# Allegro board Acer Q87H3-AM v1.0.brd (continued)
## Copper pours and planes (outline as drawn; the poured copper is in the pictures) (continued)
GND on TOP (solid shape): 141.51,243.11 141.51,234.09 140.62,233.2 129.06,233.2 127.79,231.93 127.79,222.43 126.89,221.53 126.89,219.4 126.65,219.16 126.65,217.56 126.55,217.46 125.94,217.46 125.84,217.56 125.84,220.48 124.87,221.44 124.87,222.16 124.11,222.92 124.11,223.81 125.76,225.46 125.76,227.49 124.62,228.63 124.62,236.25 125.51,237.14 125.51,243.11 125.89,243.49 141.13,243.49
GND on TOP (solid shape): 119.03,20.61 119.03,16.92 119.29,16.67 121.06,16.67 121.44,17.05 121.44,17.56 121.57,17.69 122.33,17.69 122.59,17.94 122.59,18.45 122.71,18.57 126.27,18.57 128.56,16.29 128.56,15.5 128.43,15.37 127.67,15.37 127.16,15.88 125.46,15.88 125.23,15.65 114,15.65 113.77,15.88 112.83,15.88 112.61,15.65 108.16,15.65 107.91,15.91 107.91,16.8 108.16,17.05 113.06,17.05 113.82,17.81 116.11,17.81 116.36,18.07 116.36,20.73 116.49,20.86 118.78,20.86
GND on TOP (solid shape): 30.77,71.15 31.78,71.15 32.42,70.52 31.78,69.88 30.77,69.88 30.77,66.71 27.72,66.71 27.72,69.88 26.7,69.88 26.07,70.52 26.7,71.15 27.72,71.15 27.72,75.6 30.77,75.6
GND on TOP (solid shape): 55.1,89.75 55.1,89.38 55.08,89.36 55.01,89.27 54.99,89.15 55.12,88.91 55.4,88.9 55.42,88.91 55.59,88.85 55.74,88.7 55.79,88.7 55.83,88.66 55.99,88.66 56.1,88.56 56.09,88.54 56.09,88.42 56.13,88.3 56.13,88.29 56.13,88.27 56.3,88.11 56.3,87.73 56.24,87.67 56.06,87.67 56.05,87.68 56.04,87.66 55.91,87.66 55.81,87.56 55.78,87.59 55.12,87.59 55.11,87.6 54.84,87.66 54.61,87.53 54.59,87.51 54.52,87.51 54.52,87.57 54.12,87.57 53.98,87.7 53.98,88.48 53.78,88.68 53.78,89.01 53.86,89.08 53.86,89.32 53.81,89.36 53.81,89.57 53.87,89.63 54.1,89.63 54.21,89.52 54.52,89.52 54.85,89.85 55,89.85
GND on TOP (solid shape): 55.46,101.78 55.46,101.41 55.38,101.04 55.75,100.94 55.83,100.94 55.86,100.87 55.86,100.72 55.85,100.71 55.8,100.62 55.78,100.53 55.61,100.36 55.25,100.36 54.98,100.1 54.85,100.09 54.74,100.04 54.73,100.03 54.47,100.03 54.42,100.08 54.39,100.14 54.35,100.19 54.34,100.26 54.39,100.31 54.59,100.64 54.34,100.92 54.28,100.97 54.29,101.04 54.36,101.33 54.23,101.59 54.2,101.64 54.22,101.69 54.27,101.79 54.29,101.89 54.34,101.94 55.3,101.94
GND on TOP (solid shape): 51.85,88.44 52.19,88.16 52.59,88.35 52.63,88.39 52.68,88.38 52.81,88.35 52.94,88.37 52.99,88.37 53.03,88.34 53.12,88.21 53.25,88.13 53.29,88.09 53.3,88.04 53.34,87.82 53.54,87.7 53.57,87.69 53.57,87.6 53.55,87.59 53.37,87.39 53.43,87.14 53.46,87.11 53.34,86.99 53.23,86.99 53.22,87.01 53.03,87.16 52.79,87.1 52.76,87.08 52.55,87.29 52.55,87.31 52.43,87.56 52.15,87.58 51.98,87.58 51.91,87.64 51.92,87.66 51.79,87.91 51.51,87.93 51.44,87.99 51.44,88.34 51.54,88.44
GND on TOP (solid shape): outline of 91 points within 42.5,91.29 49.05,96.68
GND on TOP (solid shape): 54.66,106.86 54.66,106.85 54.66,106.43 54.66,106.36 54.67,106.27 54.78,106.07 54.97,105.96 54.99,105.96 55.03,105.92 55.67,105.92 55.78,105.8 55.78,104.51 55.78,104.5 55.73,104.35 55.78,104.19 55.78,104.18 55.78,104.1 55.75,104.02 55.67,104 55.34,103.72 55.67,103.44 55.75,103.42 55.78,103.34 55.78,103.17 55.78,103.13 55.78,103.04 55.62,102.88 55.22,102.88 55.19,102.86 54.68,102.86 54.59,102.94 54.59,103.01 54.58,103.06 54.56,103.13 54.52,103.19 54.52,103.24 54.54,103.27 54.69,103.42 54.75,103.63 54.73,103.76 54.67,103.87 54.54,103.99 54.38,104.04 54.33,104.06 54.3,104.09 54.3,104.18 54.28,104.26 54.3,104.3 54.34,104.33 54.61,104.65 54.46,105.04 54.29,105.12 54.11,105.11 54.05,105.13 54.02,105.19 54.02,105.38 54.05,105.41 54.1,105.51 54.11,105.62 54.09,105.7 54,105.82 54,105.92 53.98,105.94 53.96,106 53.99,106.05 54.11,106.27 54.02,106.5 54,106.51 54,106.79 53.76,107.04 53.76,107.15 53.85,107.25 54.27,107.25
GND on TOP (solid shape): outline of 259 points within 9.63,74.4 18.63,83.4
GND on TOP (solid shape): outline of 259 points within 75.67,2.01 84.67,11.01
GND on TOP (solid shape): outline of 259 points within 75.67,229.34 84.67,238.34
GND on TOP (solid shape): outline of 259 points within 75.67,74.4 84.67,83.4
GND on TOP (solid shape): outline of 259 points within 233.15,2 242.15,11
GND on TOP (solid shape): outline of 259 points within 233.15,206.48 242.15,215.48
GND on TOP (solid shape): outline of 259 points within 233.15,74.4 242.15,83.4
GND on TOP (solid shape): outline of 244 points within 50.18,89.55 56.07,99.66
GND on TOP (solid shape): outline of 480 points within 41.27,98.6 47.91,103.91
GND on TOP (solid shape): outline of 1122 points within 145.03,123.21 176.44,146.07
GND on BOTTOM (solid shape): 38.01,87.03 38.01,85.12 37.24,84.36 35.59,84.36 35.47,84.49 35.47,86.92 35.96,87.41 37.62,87.41
GND on BOTTOM (solid shape): 55.66,233.08 55.66,225.71 55.28,225.33 48.29,225.33 47.78,225.84 47.78,234.6 48.09,234.91 53.83,234.91
GND on BOTTOM (solid shape): 69.76,101.76 69.76,100.74 69.63,100.62 64.8,100.62 64.68,100.74 64.68,101.76 64.8,101.89 69.63,101.89
GND on BOTTOM (solid shape): 207.04,242.98 207.04,231.81 206.79,231.55 202.22,231.55 201.71,232.06 201.71,243.11 202.09,243.49 206.53,243.49
GND on BOTTOM (solid shape): 230.28,152.18 230.28,148.88 230.16,148.75 226.85,148.75 226.73,148.88 226.73,152.18 226.85,152.31 230.16,152.31
GND on BOTTOM (solid shape): 238.16,192.18 238.16,187.48 237.59,186.91 234.28,186.91 230.46,190.74 230.46,191.8 231.1,192.44 237.9,192.44
GND on BOTTOM (solid shape): 48.76,97.13 48.76,94.34 48.48,94.06 48.06,94.06 47.98,94.14 47.98,97.1 48.18,97.3 48.59,97.3
GND on BOTTOM (solid shape): 73.44,216.82 73.44,213.52 73.18,213.27 69.76,213.27 69.5,213.52 69.5,216.82 69.76,217.08 73.18,217.08
GND on BOTTOM (solid shape): 37.75,108.62 38.51,108.62 39.28,107.86 39.28,106.84 39.15,106.71 38.26,106.71 37.75,107.22 36.1,107.22 35.97,107.35 35.97,109.63 36.1,109.76 36.61,109.76
GND on BOTTOM (solid shape): 227.74,174.66 227.74,165.13 227.24,164.62 225.33,164.62 224.95,165.01 224.95,174.66 224.96,174.67 224.96,175.28 225.28,175.6 226.8,175.6
GND on BOTTOM (solid shape): 133.76,182.91 133.76,171.48 133.26,170.97 132.75,170.97 132.37,171.36 132.37,182.91 132.49,183.04 133.64,183.04
GND on BOTTOM (solid shape): 179.61,243.11 179.61,235.3 178.91,234.6 173.39,234.6 172.75,235.24 172.75,240.44 171.55,241.65 152.05,241.65 151.29,240.89 151.29,235.62 150.78,235.11 143.03,235.11 142.02,236.13 142.02,243.11 142.4,243.49 179.23,243.49
GND on BOTTOM (solid shape): 201.2,243.11 201.2,232.32 200.69,231.81 199.8,231.81 199.3,232.32 199.3,234.47 198.41,235.36 185.07,235.36 184.82,235.11 184.82,232.19 184.56,231.93 180.75,231.93 180.12,232.57 180.12,243.11 180.5,243.49 200.82,243.49
GND on BOTTOM (solid shape): 153.58,182.79 153.58,179.23 152.81,178.47 152.81,171.1 152.69,170.97 152.31,170.97 152.18,171.1 152.18,171.74 151.29,172.63 151.29,175.8 150.78,176.31 150.78,182.79 151.04,183.04 153.32,183.04
GND on BOTTOM (solid shape): 174.91,184.31 174.91,179.74 173.26,178.09 173.26,172.24 173.13,172.12 172.88,172.12 171.23,173.77 171.23,180.37 171.99,181.13 171.99,183.55 173.01,184.56 174.66,184.56
GND on BOTTOM (solid shape): 225.46,242.6 225.46,232.06 225.08,231.68 224.06,231.68 223.55,232.19 223.55,235.24 223.24,235.55 209.52,235.55 209.33,235.36 209.33,231.93 209.07,231.68 208.06,231.68 207.55,232.19 207.55,242.98 208.06,243.49 224.57,243.49
GND on BOTTOM (solid shape): 159.16,126.4 159.16,124.87 159.54,124.49 162.97,124.49 163.48,125 163.48,126.4 163.74,126.65 168.94,126.65 169.2,126.4 169.2,123.35 169.07,123.22 150.15,123.22 149.89,123.48 149.89,126.27 150.15,126.52 151.92,126.52 152.31,126.14 152.31,124.87 152.69,124.49 154.85,124.49 155.23,124.87 155.23,126.27 155.61,126.65 158.91,126.65
GND on BOTTOM (solid shape): 141.51,242.86 141.51,223.55 140.11,222.16 138.59,222.16 137.95,222.79 137.95,232.7 137.45,233.2 131.35,233.2 130.84,232.7 130.84,224.06 129.95,223.17 128.07,223.17 128.05,223.2 126.75,221.9 125.13,221.9 124.11,222.92 124.11,223.81 125.76,225.46 125.76,227.49 124.62,228.63 124.62,236.25 125.51,237.14 125.51,243.11 125.89,243.49 140.88,243.49
GND on BOTTOM (solid shape): 30.77,71.15 31.78,71.15 32.42,70.52 31.78,69.88 30.77,69.88 30.77,66.71 27.72,66.71 27.72,69.88 26.7,69.88 26.07,70.52 26.7,71.15 27.72,71.15 27.72,75.6 30.77,75.6
GND on BOTTOM (solid shape): 43.72,103.64 43.72,101.92 43.53,101.73 43.53,98.14 43.53,98.14 43.53,97.5 43.34,97.31 42.96,97.31 42.83,97.44 42.83,100.49 42.45,100.87 42.45,101.38 41.95,101.88 41.93,101.97 41.99,102.04 42.21,102.49 41.8,102.77 41.72,102.8 41.69,102.88 41.69,103.79 41.72,103.82 41.79,103.85 41.86,103.81 42.19,103.69 42.48,103.89 42.5,103.92 43.44,103.92
GND on BOTTOM (solid shape): outline of 223 points within 39.32,211.73 50.66,216.58
GND on BOTTOM (solid shape): outline of 223 points within 54.05,210.71 65.39,215.56
GND on BOTTOM (solid shape): outline of 223 points within 54.65,124.74 65.99,129.58
GND on BOTTOM (solid shape): outline of 617 points within 225.84,223.81 243.49,243.49
GND on BOTTOM (solid shape): outline of 49857 points within 93.83,37.88 226.09,128.72
GND on PWR (solid shape): 238.16,192.03 238.16,183.07 236.98,181.9 217.87,181.9 217.46,182.31 217.46,186.06 217.74,186.34 221.55,186.34 222.41,187.2 222.41,190.25 222.82,190.66 229.04,190.66 230.82,192.44 237.75,192.44
GND on PWR (solid shape): 76.72,65.13 77.01,64.84 77.01,64.06 77.37,63.7 78.19,63.7 78.25,63.63 78.25,63.16 78.14,63.06 77.09,63.06 76.68,62.65 76.42,62.65 75.85,63.22 72.37,63.22 72.23,63.36 72.23,64.8 72.58,65.15 76.72,65.15
GND on PWR (solid shape): 189.52,185.17 189.52,182.05 189.1,181.64 188.08,181.64 188,181.69 187.98,181.78 187.6,182.32 187.21,181.78 187.2,181.69 187.12,181.64 182.69,181.64 182.28,182.05 182.28,183.32 181.52,184.09 181.52,185.17 181.93,185.58 189.1,185.58
GND on PWR (solid shape): 179.74,26.83 181.13,26.83 181.34,26.63 181.34,25.36 175.67,19.7 175.67,17.03 175.31,16.67 159.27,16.67 158.91,17.03 158.91,17.96 159.01,18.07 161.3,18.07 161.7,18.47 161.7,19.99 162.59,20.88 162.59,24.93 162.77,25.1 176.14,25.1 177.7,26.66 177.78,26.69 177.85,26.65 178.57,26.74 178.09,27.27 178,27.29 177.96,27.37 177.96,27.72 178.09,27.85 178.72,27.85
GND on PWR (solid shape): 46.27,22.22 46.36,22.17 46.36,22.07 46.72,21.47 47.08,22.07 47.08,22.17 47.17,22.22 50.1,22.22 50.19,22.16 50.17,22.04 50.13,21.5 50.66,21.4 50.77,21.4 50.82,21.32 50.82,21.15 50.66,20.99 48.25,20.99 48.02,20.73 45.4,20.73 45.24,20.89 45.24,22.08 45.38,22.22
GND on PWR (solid shape): outline of 115 points within 43.09,6.64 47.71,22.51
GND on PWR (solid shape): outline of 119 points within 215.37,164.62 232.44,181.13
GND on PWR (solid shape): outline of 149 points within 70.77,37.66 79.38,56.42
GND on PWR (solid shape): outline of 151 points within 158.78,30.51 172.9,35.97
GND on PWR (solid shape): outline of 164 points within 41.64,105.7 45.63,120.3
GND on PWR (solid shape): outline of 163 points within 150.02,168.18 155.23,185.59
GND on PWR (solid shape): outline of 180 points within 29.95,96.91 38.49,99.83
GND on PWR (solid shape): outline of 208 points within 93.68,93.05 107.93,106.28
GND on PWR (solid shape): outline of 202 points within 132.37,167.55 136.56,187.36
GND on PWR (solid shape): outline of 204 points within 29.06,101.48 38.21,105.82
GND on PWR (solid shape): outline of 219 points within 27.39,76.01 31.48,81.01
GND on PWR (solid shape): outline of 241 points within 143.54,180.88 152.31,189.01
GND on PWR (solid shape): outline of 268 points within 76.93,55.31 84.82,66.15
GND on PWR (solid shape): outline of 259 points within 163.61,167.93 175.42,187.36
GND on PWR (solid shape): outline of 329 points within 106.97,195.49 117.02,211.74
GND on PWR (solid shape): outline of 424 points within 52.1,105.44 59.21,112.24
GND on PWR (solid shape): outline of 507 points within 38.44,97.7 42.58,102.93
GND on PWR (solid shape): outline of 560 points within 22.69,32.09 42.12,43.54
GND on PWR (solid shape): outline of 562 points within 197.26,221.27 210.85,243.49
GND on PWR (solid shape): outline of 726 points within 50.77,85.76 65.06,94.52
GND on PWR (solid shape): outline of 828 points within 18.5,14.15 42.15,26.02
GND on PWR (solid shape): outline of 1060 points within 225.84,205.14 243.49,243.49
GND on PWR (solid shape): outline of 1040 points within 42.83,25.81 64.6,45.12
GND on PWR (solid shape): outline of 1156 points within 105.49,171.53 141.09,197.21
GND on PWR (solid shape): outline of 1159 points within 185.25,9.7 206.26,37.57
GND on PWR (solid shape): outline of 1306 points within 16.97,42.76 36.81,61.45
GND on PWR (solid shape): outline of 1494 points within 123.37,209.46 147.48,243.49
GND on PWR (solid shape): outline of 1700 points within 177.55,202.22 201.2,243.49
GND on PWR (solid shape): outline of 2121 points within 207.42,204.5 232.57,243.49
GND on PWR (solid shape): outline of 3921 points within 142.02,204.88 180.63,243.49
GND on PWR (solid shape): outline of 6569 points within 37.29,193.89 109,240.32
GND on PWR (solid shape): outline of 7018 points within 101.94,37.93 139.68,55.73
GND on PWR (solid shape): outline of 10410 points within 46.06,108.67 92.56,186.04
GND on PWR (solid shape): outline of 17614 points within 163.61,37.93 227.01,128.76
GND on PWR (solid shape): outline of 23484 points within 101.3,60.41 238.72,181.91
GND on GND (solid shape): outline of 184251 points within 0.51,0.51 243.49,243.49
GNDA1 on TOP (solid shape): 73.06,150.27 73.26,150.07 75.06,150.07 75.19,149.94 75.19,148.29 75.09,148.19 74.15,148.19 73.77,147.81 73.77,147.3 73.49,147.02 72.63,147.02 72.04,147.61 72.04,151.29 73.06,151.29
GNDA1 on TOP (solid shape): 65.46,148.19 65.53,148.19 65.53,148.19 67.16,148.19 67.16,148.19 69.04,148.19 69.2,148.04 69.2,147.38 69.15,147.33 68.36,147.33 68.28,147.25 65.35,147.25 65.28,147.17 65.18,147.17 64.93,146.92 64.93,145.07 64.8,144.94 63.91,144.94 63.79,145.07 63.79,148.11 63.85,148.18 64,148.18 64.12,148.29 65.36,148.29
GNDA1 on PWR (solid shape): 73.13,151.22 73.13,150.45 73.49,150.1 75.02,150.1 75.17,149.95 75.17,148.32 75.02,148.17 74.13,148.17 73.77,147.81 73.77,147.3 73.49,147.02 72.6,147.02 72.24,146.66 72.24,146.03 72.09,145.88 70.97,145.88 70.46,146.39 65.74,146.39 65.26,145.9 65.26,145.27 64.98,144.99 63.72,144.99 63.58,145.13 63.58,148.13 63.78,148.32 65.11,148.32 65.36,148.06 69.96,148.06 70.44,148.55 70.44,149.46 70.08,149.82 69.45,149.82 69.3,149.97 69.3,150.45 69.83,150.98 71.35,150.98 71.73,151.37 72.98,151.37
P2VIN on TOP (solid shape): outline of 182 points within 173.64,25.56 195.18,37.5
P2VIN on BOTTOM (solid shape): outline of 179 points within 178.85,25.94 195.18,35.34
P2VIN on PWR (solid shape): outline of 263 points within 173.64,25.48 195.18,37.57
81038_VIN on TOP (solid shape): 50.59,35.64 50.78,35.64 51.54,34.88 51.54,34.81 51.52,34.79 51.52,34.72 51.48,34.68 50.96,34.68 50.95,34.69 50.21,34.69 49.44,35.47 49.44,36.04 49.18,36.29 49.18,36.61 49.25,36.67 49.56,36.67
+ATX_3VSB on TOP (solid shape): 232.57,41.56 232.57,39.78 232.44,39.66 231.43,39.66 230.92,40.16 230.92,41.05 231.55,41.69 232.44,41.69
+ATX_3VSB on TOP (solid shape): 36.86,87.66 36.99,87.66 37.12,87.54 37.12,87.2 36.86,86.95 36.82,86.93 36.77,86.9 35.47,86.9 35.34,87.03 35.34,87.75 35.59,88.01 36.52,88.01
+ATX_3VSB on TOP (solid shape): 115.25,29.73 116.36,29.73 116.52,29.57 116.52,29.17 115.98,28.63 115.98,20.1 115.44,19.55 113.81,19.55 113.72,19.46 111.79,19.46 111.41,19.08 111.41,17.69 111.03,17.3 107.86,17.3 107.47,17.69 107.47,18.83 112.3,23.65 112.3,27.19 113.57,28.46 113.57,28.99 113.44,29.12 113.44,30 113.63,30.2 114.78,30.2
+ATX_5VSB on TOP (solid shape): 11.97,211.74 11.97,210.73 12.22,210.47 13.88,210.47 14.13,210.22 14.13,209.07 13.88,208.82 10.45,208.82 10.19,209.07 10.19,211.74 10.45,212 11.72,212
+ATX_5VSB on TOP (solid shape): 5.62,34.2 5.62,32.74 6.2,32.15 15.41,32.15 17.69,29.88 17.69,29.12 17.81,28.99 17.81,28.38 17.53,28.1 16.87,28.1 16.47,28.51 16.47,29.45 15.11,30.8 5.96,30.8 4.41,32.35 2.38,32.35 2.06,32.67 2.06,33.94 2.45,34.32 3.46,34.32 3.72,34.58 3.72,35.08 4.73,35.08
+ATX_5VSB on TOP (solid shape): outline of 152 points within 116.62,3.59 135.03,25.43
+ATX_5VSB on BOTTOM (solid shape): 3,34.12 3,33.2 2.57,32.77 1.51,32.77 1.26,33.03 1.26,34.17 1.51,34.42 2.7,34.42
+DDR_VTTR on TOP (solid shape): outline of 82 points within 87.92,27.46 99.73,75.6
+DIMM_5VDUAL on TOP (solid shape): outline of 82 points within 176.82,15.97 195.18,30.46
+DIMM_5VDUAL on TOP (solid shape): outline of 145 points within 142.53,7.65 154.85,27.39
+DIMM_5VDUAL on BOTTOM (solid shape): 195.18,30.18 195.18,27.41 193.71,25.94 185.38,25.94 185.12,26.19 185.12,26.96 185.51,26.96 185.51,26.88 185.52,26.8 185.54,26.72 185.57,26.64 185.61,26.57 185.65,26.5 185.7,26.43 185.75,26.37 185.81,26.32 185.88,26.27 185.95,26.23 186.02,26.2 186.1,26.17 186.18,26.15 186.26,26.14 186.34,26.14 186.42,26.15 186.5,26.16 186.58,26.18 186.66,26.21 186.73,26.25 186.8,26.3 186.86,26.35 186.92,26.4 186.97,26.46 187.02,26.53 187.05,26.6 187.09,26.68 187.11,26.76 187.13,26.84 187.13,26.92 187.13,27 187.13,27.08 187.11,27.16 187.09,27.23 187.05,27.31 187.02,27.38 186.97,27.45 186.92,27.51 186.86,27.57 186.8,27.62 186.73,27.66 186.66,27.7 186.58,27.73 186.5,27.75 186.42,27.76 186.34,27.77 186.26,27.77 186.18,27.76 186.1,27.74 186.02,27.71 185.95,27.68 185.88,27.64 185.81,27.59 185.75,27.54 185.7,27.48 185.65,27.42 185.61,27.35 185.57,27.27 185.54,27.2 185.52,27.12 185.51,27.04 185.51,26.96 185.12,26.96 185.12,27.39 188.2,30.46 194.9,30.46
+DIMM_5VDUAL on PWR (solid shape): outline of 1388 points within 143.85,10.37 195.18,30.46
+DP_PWR on TOP (solid shape): 228.25,224.57 228.25,223.3 228.51,223.04 229.14,223.04 229.52,222.66 230.79,222.66 231.05,222.41 231.05,219.36 230.92,219.23 229.52,219.23 227.74,221.01 227.74,221.52 226.73,222.54 226.73,223.68 225.2,225.2 225.2,226.09 225.58,226.47 226.35,226.47
+DP_PWR on BOTTOM (solid shape): 198.41,234.22 198.41,232.06 197.01,230.66 197.01,225.84 196.76,225.58 195.49,225.58 195.36,225.71 195.36,231.05 197.26,232.95 197.26,233.33 197.01,233.59 195.99,233.59 195.87,233.71 195.87,234.22 196.12,234.47 198.15,234.47
+DP_PWR on BOTTOM (solid shape): 222.79,234.47 222.79,232.32 225.33,229.78 225.33,228 226.85,226.47 226.85,225.46 226.6,225.2 225.58,225.2 225.33,225.46 225.33,226.35 224.31,227.36 222.03,227.36 221.39,228 221.39,233.46 221.27,233.59 220.25,233.59 220,233.84 220,234.73 220.25,234.98 222.28,234.98
+DP_VCC3 on TOP (solid shape): 229.27,218.6 231.05,218.6 231.17,218.47 231.17,217.71 230.92,217.46 229.27,217.46 228.76,217.96 226.6,217.96 225.84,218.73 225.84,219.49 226.09,219.74 228.12,219.74
+DVI_VCC on TOP (solid shape): 172.12,218.47 172.12,215.17 171.99,215.04 170.59,215.04 170.47,215.17 170.47,216.06 169.96,216.57 169.96,218.22 170.09,218.35 170.85,218.35 171.1,218.6 171.99,218.6
+DVI_VCC on BOTTOM (solid shape): outline of 330 points within 155.23,233.92 162.97,238.92
+DVI_VGA_VCC on TOP (solid shape): 171.99,214.54 171.99,209.06 171.95,209.05 171.62,208.59 172.04,208.2 172.06,208.2 172.6,207.65 172.6,206.51 172.42,206.33 170.75,206.33 170.16,205.75 170.16,205.34 169.73,204.91 167.09,204.91 166.78,205.21 166.78,205.9 167.16,206.28 168.51,206.28 170.17,207.94 170.17,212.29 169.45,213.01 168.94,213.01 168.31,213.65 168.31,214.5 168.52,214.71 170.04,214.71 170.12,214.79 171.74,214.79
+LDOVDD on TOP (solid shape): 18.96,229.65 18.96,229.47 18.9,229.27 18.96,229.06 18.96,228.51 18.83,228.38 17.84,228.38 17.33,228.89 15.27,228.89 15.15,229.01 15.15,229.78 15.27,229.9 18.7,229.9
+SPI_3P3V on TOP (solid shape): 31.4,4.11 35.85,4.11 36.1,3.86 36.1,2.97 35.97,2.84 16.92,2.84 16.67,3.1 16.67,4.25 16.92,4.5 19.49,4.5 19.82,4.17 25.63,4.17 26.45,3.35 29.09,3.35 29.37,3.63 29.37,4.37 29.62,4.62 30.89,4.62
+SROUT12 on TOP (solid shape): 62.77,226.47 62.77,222.41 62.64,222.28 60.48,222.28 60.1,222.66 58.71,222.66 57.18,224.19 56.69,224.19 56.45,224.43 56.47,224.49 56.29,224.92 55.84,224.95 55.8,224.93 55.61,225.12 55.61,225.16 55.59,225.25 55.54,225.34 55.53,225.35 55.53,225.58 55.62,225.67 56.43,225.67 56.43,225.71 57.44,225.71 57.72,225.43 57.72,225.39 58.17,224.95 58.17,224.94 58.33,224.73 58.58,224.64 58.62,224.65 58.66,224.65 58.88,224.77 59,224.98 59,224.99 59.41,225.4 59.48,225.43 59.55,225.4 60.11,225.37 60.23,225.92 60.23,226.09 60.99,226.85 62.39,226.85
+SROUT12_R on TOP (solid shape): 68.36,228.32 68.36,227.24 68.87,226.73 70.14,226.73 70.33,226.92 71.03,226.92 71.22,226.73 71.22,226.41 70.52,225.71 70.39,225.71 69.95,225.27 68.61,225.27 68.04,225.84 66.83,225.84 66.26,225.27 66.26,222.54 66.07,222.35 64.1,222.35 63.98,222.47 63.98,226.6 64.23,226.85 66.33,226.85 66.83,227.36 67.22,227.36 67.6,227.74 67.6,228.25 67.79,228.44 68.23,228.44
+USB3VCC0 on TOP (solid shape): outline of 188 points within 120.15,206.94 127.64,233.59
+USB3VCC0 on BOTTOM (solid shape): outline of 382 points within 116.24,220.12 125.25,234.47
+USB3VCC1 on TOP (solid shape): 20.73,43.85 20.73,43.47 19.97,42.7 19.97,34.27 19.46,33.76 17.56,33.76 16.92,34.4 16.92,35.21 16.67,35.47 15.65,35.47 15.15,34.96 13.72,34.96 13.6,35.08 13.6,37.12 13.11,37.6 13.11,38.26 13.24,38.39 17.43,38.39 17.69,38.64 17.69,41.05 17.3,41.43 17.3,41.94 17.81,42.45 18.83,42.45 19.34,42.96 19.34,43.72 19.59,43.97 20.61,43.97
+USBVCC0 on TOP (solid shape): outline of 219 points within 134.53,205.9 141.26,228.12
+USBVCC1 on TOP (solid shape): 145.19,232.19 145.19,217.33 143.29,215.42 143.29,214.15 142.42,213.29 142.42,211.97 142.27,211.82 140.52,211.82 140.37,211.97 140.37,215.68 141.64,216.95 141.64,225.33 142.82,225.33 142.83,225.28 142.84,225.22 142.86,225.16 142.89,225.11 142.92,225.06 142.96,225.02 143.01,224.98 143.06,224.95 143.11,224.92 143.17,224.91 143.23,224.9 143.29,224.9 143.35,224.91 143.4,224.92 143.46,224.95 143.51,224.98 143.55,225.02 143.59,225.06 143.63,225.11 143.66,225.16 143.67,225.22 143.69,225.28 143.69,225.33 143.69,225.39 143.67,225.45 143.65,225.51 143.64,225.53 143.64,225.84 143.67,225.84 143.67,226.6 143.64,226.6 143.64,226.98 143.67,226.98 143.67,227.74 142.84,227.74 142.84,226.98 142.88,226.98 142.88,226.6 142.84,226.6 142.84,225.84 142.88,225.84 142.88,225.53 142.86,225.51 142.84,225.45 142.83,225.39 142.82,225.33 141.64,225.33 141.64,229.9 140.75,230.79 138.72,230.79 138.08,230.16 138.08,228.76 137.83,228.51 135.8,228.51 135.54,228.76 135.54,232.7 135.8,232.95 144.43,232.95
+USBVCC1 on TOP (solid shape): outline of 154 points within 236.25,221.27 240.82,237.52
+USBVCC2 on TOP (solid shape): outline of 91 points within 3.7,95.18 11.21,106.84
+USBVCC3 on TOP (solid shape): outline of 113 points within 3.72,118.52 11.46,129.26
+USBVCC4 on TOP (solid shape): outline of 109 points within 3.59,136.56 12.86,143.67
+V_1P05_ME on TOP (solid shape): 81.19,68.87 81.19,68.1 79.79,66.71 77.88,66.71 76.99,65.82 72.68,65.82 72.04,66.45 71.66,66.45 71.38,66.17 70.49,66.17 70.21,66.45 64.68,66.45 64.29,66.83 64.29,68.99 64.55,69.25 80.8,69.25
+V_1P05_ME on TOP (solid shape): 44.99,98.58 44.99,97.09 46.44,95.64 46.44,94.72 46.77,94.39 47.17,94.39 47.3,94.27 47.3,93.96 47.17,93.83 45.32,93.83 45.09,94.06 44.94,94.06 44.66,94.34 43.75,94.34 43.52,94.57 43.52,94.85 44.29,95.63 44.29,98.83 44.46,98.99 44.58,98.99
+V_1P05_ME on PWR (solid shape): outline of 2647 points within 37.5,59.52 72.5,95.47
+V_1P05_PCH on TOP (solid shape): 69.25,109.25 69.25,105.32 69.12,105.19 66.33,105.19 66.2,105.32 66.2,108.62 65.69,109.13 65.69,109.89 65.82,110.01 68.49,110.01
+V_1P05_PCH on TOP (solid shape): 43.96,98.09 43.96,95.55 43.82,95.41 43.19,95.41 42.91,95.69 42.91,97.92 43.21,98.23 43.82,98.23
+V_1P05_PCH on TOP (solid shape): outline of 189 points within 68.1,69.63 94.9,88.81
+V_1P05_PCH on BOTTOM (solid shape): 82.33,85.5 82.33,84.36 82.07,84.11 78.65,84.11 78.39,84.36 78.39,85.5 78.65,85.76 82.07,85.76
+V_1P05_PCH on BOTTOM (solid shape): 69.76,100.24 69.76,99.37 69.72,99.3 69.65,99.27 69.57,99.27 69.5,99.25 69.24,99.25 69.02,99.09 68.84,99.09 68.49,99.27 68.14,99.09 65.06,99.09 64.93,99.22 64.93,100.24 65.06,100.36 69.63,100.36
+V_1P05_PCH on BOTTOM (solid shape): outline of 291 points within 42.83,94.27 51.27,101.76
+V_1P05_PCH on PWR (solid shape): outline of 12405 points within 32.98,62.69 84.82,125.2
+V_3P3_LAN on TOP (solid shape): 59.85,208.44 59.85,206.79 60.23,206.41 62.01,206.41 62.14,206.28 62.14,204.38 61.88,204.12 61.37,204.12 58.96,206.53 58.96,208.44 59.09,208.57 59.72,208.57
+V_3P3_LAN on TOP (solid shape): outline of 86 points within 94.39,202.22 105.32,208.57
+V_3P3_LAN on BOTTOM (solid shape): outline of 194 points within 17.18,196.44 23.72,199.8
+VCORE on TOP (solid shape): outline of 3898 points within 134.27,124.75 212.76,177.2
+VCORE on BOTTOM (solid shape): outline of 4072 points within 134.27,124.75 210.73,173.51
+VCORE on PWR (solid shape): outline of 3170 points within 134.27,124.75 212.76,178.09
+VDIMM on TOP (solid shape): 103.79,92.49 103.79,88.17 101.51,85.88 101.51,82.96 100.87,82.33 96.81,82.33 94.14,85 94.14,92.11 94.77,92.74 103.54,92.74
+VDIMM on TOP (solid shape): 106.59,32.93 106.59,28.1 105.32,26.83 102.78,26.83 102.39,27.21 102.39,32.93 102.65,33.18 106.33,33.18
+VDIMM on TOP (solid shape): 96.68,78.14 96.68,62.01 94.6,59.93 93.94,59.93 93.81,60.05 93.81,61.93 95.21,63.33 95.21,76.44 93.89,77.76 93.89,78.77 94.39,79.28 95.54,79.28
+VDIMM on TOP (solid shape): outline of 156 points within 130.72,27.85 155.61,36.35
+VDIMM on TOP (solid shape): outline of 150 points within 147.94,118.52 169.45,122.84
+VDIMM on BOTTOM (solid shape): outline of 154 points within 130.72,28.23 155.48,33.43
+VDIMM on BOTTOM (solid shape): 169.07,122.59 169.07,120.68 168.82,120.43 166.63,120.43 166.63,120.45 165.8,120.45 165.8,120.43 165.68,120.43 165.68,120.45 164.85,120.45 164.85,120.43 163.1,120.43 163,120.53 161.84,120.53 161.74,120.43 161.07,120.43 160.94,120.3 160.94,119.63 160.92,119.61 160.92,119.13 160.74,118.96 160.08,118.96 160.04,118.99 160.04,119.06 159.67,119.67 159.35,119.03 159.35,118.99 159.32,118.96 159.11,118.96 159.09,118.98 159.09,119 158.77,119.67 158.45,119.01 158.45,118.98 158.43,118.96 156.39,118.96 156.37,118.98 156.37,119.03 156.03,119.67 155.69,119.03 155.69,118.99 155.66,118.96 154.57,118.96 154.53,118.99 154.53,119.02 154.22,119.67 153.85,119.05 153.85,119 153.8,118.96 150.95,118.96 149.77,120.14 149.77,122.46 150.15,122.84 168.82,122.84
+VDIMM on PWR (solid shape): outline of 20764 points within 92.92,27.77 215.63,122.84
+VGA_VCC on TOP (solid shape): 169.7,218.47 169.7,216.44 170.09,216.06 170.09,215.04 169.96,214.92 168.43,214.92 168.18,214.66 167.55,214.66 167.29,214.92 167.27,214.92 167.14,215.04 167.14,215.4 167.34,215.6 167.34,217.23 167.33,217.24 167.33,218.08 167.49,218.24 167.95,218.24 168.43,218.73 169.45,218.73
ATX_3VSB_EN on TOP (solid shape): 121.06,21.5 121.06,19.97 121.32,19.72 122.08,19.72 122.21,19.59 122.21,17.94 122.08,17.81 121.44,17.81 120.96,18.3 119.51,18.3 119.41,18.4 119.41,21.5 119.54,21.62 120.94,21.62
AUGND on TOP (solid shape): 12.99,225.97 12.99,225.46 12.86,225.33 9.56,225.33 9.43,225.46 9.43,226.73 9.56,226.85 12.1,226.85
AUGND on TOP (solid shape): 17.75,231.8 17.94,231.76 18.13,231.8 18.14,231.81 18.62,231.81 18.63,231.8 18.74,231.76 18.85,231.76 18.88,231.76 18.96,231.68 18.96,230.28 18.83,230.16 16.42,230.16 16.29,230.28 16.29,231.55 16.54,231.81 17.73,231.81
AUGND on TOP (solid shape): outline of 98 points within 88.93,238.67 104.68,243.49
AUGND on TOP (solid shape): outline of 259 points within 29.95,229.34 38.95,238.34
AUGND on BOTTOM (solid shape): outline of 298 points within 88.81,233.59 104.68,243.49
AUGND on PWR (solid shape): outline of 6398 points within 0.51,175.29 104.68,243.49
AUGND on GND (solid shape): outline of 6355 points within 0.51,175.29 104.68,243.49
BZ_P on TOP (solid shape): 217.2,116.36 217.2,113.7 224.19,106.71 225.2,106.71 226.35,105.57 228.63,105.57 228.89,105.32 228.89,104.43 229.65,103.66 232.57,103.66 232.7,103.54 232.7,102.65 232.57,102.52 229.9,102.52 229.52,102.14 225.46,102.14 225.33,102.27 225.33,104.3 225.08,104.55 222.66,104.55 214.54,112.68 214.54,116.36 214.79,116.62 216.95,116.62
DDID_LEVEL_SF on TOP (solid shape): 179.1,213.9 179.1,212.63 178.98,212.5 177.96,212.5 177.45,213.01 176.94,213.01 176.82,213.14 176.82,213.9 176.94,214.03 178.98,214.03
DDID_LEVEL_SF on TOP (solid shape): 174.43,214 174.94,214 175.17,213.77 175.17,212.5 175.04,212.38 174.15,212.38 173.51,213.01 173.01,213.01 172.88,213.14 172.88,213.87 172.99,213.98 173.59,213.98 173.64,214.03 174.41,214.03
DP_PWR_FUSE on TOP (solid shape): 229.98,216.36 229.98,212.58 228.89,211.49 225.71,211.49 225.46,211.74 225.46,213.52 225.71,213.77 227.11,213.77 227.36,214.03 227.36,217.33 227.49,217.46 228.89,217.46
FAN_CTL2_OP_P1 on TOP (solid shape): 118.9,191.42 118.9,189.73 118.75,189.57 116.49,189.57 116.36,189.69 116.36,191.42 116.49,191.55 118.78,191.55
FAN_CTL2_OP_P1_R on TOP (solid shape): 118.9,193.83 118.9,192.95 119.41,192.44 120.81,192.44 121.06,192.18 121.06,190.91 120.94,190.79 119.16,190.79 119.03,190.91 119.03,191.68 118.9,191.8 117,191.8 116.87,191.93 116.87,193.83 117.25,194.22 118.52,194.22
G4_VCC on TOP (solid shape): 150.08,186.53 150.08,185.64 149.77,185.33 147.61,185.33 147.48,185.2 147.48,184.69 147.42,184.63 146.78,184.63 146.72,184.69 146.72,185.52 147.04,185.83 148.69,185.83 148.88,186.02 148.88,186.41 149.07,186.6 150.02,186.6
ILAN_CTRL on TOP (solid shape): 72.17,211.36 72.17,211.31 72.12,211.11 72.17,210.9 72.17,205.14 72.04,205.01 69.63,205.01 69.5,205.14 69.5,209.33 69.63,209.46 70.52,209.46 71.74,210.67 71.74,211.18 71.79,211.23 71.79,211.36 71.91,211.49 72.04,211.49
INT_VIN on TOP (solid shape): 9.68,184.44 9.68,179.74 8.92,178.98 7.65,178.98 7.53,179.1 7.53,182.66 6.64,183.55 6.64,184.18 7.02,184.56 9.56,184.56
LPTVCC on TOP (solid shape): 171.1,13.11 171.1,12.48 170.47,11.84 169.45,11.84 168.82,12.48 168.82,13.24 168.94,13.37 170.85,13.37
LPTVCC on TOP (solid shape): 155.33,13.24 155.33,12.45 154.72,11.84 153.7,11.84 153.09,12.45 153.09,13.27 153.19,13.37 155.2,13.37
LPTVCC on TOP (solid shape): 162.49,13.34 162.49,12.33 161.98,11.82 160.96,11.82 160.46,12.33 160.46,13.34 160.48,13.37 162.47,13.37
LPTVCC on TOP (solid shape): 179.99,13.37 179.99,12.55 179.76,12.33 179.15,12.33 178.59,11.77 177.38,11.77 177.05,11.44 176.69,11.44 176.49,11.64 176.49,12.55 177.36,13.43 179.93,13.43
LPTVCC on TOP (solid shape): 184.69,14.13 184.69,11.59 183.79,10.69 182.91,10.69 182.91,10.45 181.52,10.45 180.88,11.08 180.88,11.97 182.15,11.97 182.15,11.79 182.13,11.76 182.11,11.7 182.1,11.64 182.1,11.58 182.1,11.52 182.12,11.47 182.14,11.41 182.16,11.36 182.2,11.31 182.24,11.27 182.29,11.23 182.34,11.2 182.39,11.18 182.45,11.16 182.51,11.16 182.57,11.16 182.63,11.17 182.68,11.18 182.74,11.21 182.79,11.24 182.83,11.28 182.87,11.32 182.9,11.37 182.93,11.42 182.95,11.48 182.96,11.54 182.96,11.6 182.96,11.65 182.95,11.71 182.93,11.77 182.91,11.79 182.91,12.41 182.56,12.76 182.15,12.76 182.15,12.8 181.39,12.8 181.39,11.97 180.88,11.97 180.88,14.13 181.13,14.38 184.44,14.38
Net_146 on TOP (solid shape): outline of 230 points within 182.46,106.16 188.2,111.9
Net_147 on TOP (solid shape): outline of 230 points within 182.46,142.16 188.21,147.9
Net_148 on TOP (solid shape): outline of 240 points within 120.93,123.65 127.69,130.41
P2PHASE on TOP (solid shape): 164.65,31.5 164.65,30.33 165.23,29.75 166.99,29.75 167.58,30.35 167.58,31.57 167.67,31.66 172.37,31.66 173.74,30.28 176.92,30.28 177.2,30 177.2,29.14 177.18,29.13 177.2,29.12 177.2,28.61 177.38,28.43 177.38,28 177.2,27.82 177.2,27.24 175.8,25.84 155.58,25.84 154.21,27.21 154.21,29.75 156.12,31.66 164.5,31.66
P2PHASE on BOTTOM (solid shape): 164.65,31.5 164.65,30.33 165.23,29.75 167.01,29.75 167.57,30.31 167.57,31.55 167.67,31.66 172.37,31.66 173.74,30.28 176.92,30.28 177.2,30 177.2,27.21 175.84,25.85 155.57,25.85 154.21,27.21 154.21,29.75 156.12,31.66 164.5,31.66
P2PHASE on PWR (solid shape): 164.65,31.47 164.65,30.32 165.26,29.75 166.99,29.75 167.6,30.35 167.6,31.55 167.7,31.66 172.4,31.66 172.91,31.15 172.91,31.14 173.74,30.31 176.91,30.31 177.2,30 177.2,27.24 175.82,25.86 155.59,25.86 154.21,27.24 154.21,29.72 156.15,31.66 164.47,31.66
PCH_1P05_N4 on TOP (solid shape): 93.25,95.41 93.25,90.46 93,90.2 89.82,90.2 89.57,90.46 89.57,93.89 89.82,94.14 91.35,94.14 91.6,94.39 91.6,95.41 91.85,95.66 93,95.66
PHASE1 on TOP (solid shape): 162.82,185.38 162.82,180.5 163.71,179.61 167.9,179.61 168.43,179.08 168.43,176.71 168.16,176.44 166.15,176.44 165.01,177.58 164.37,177.58 163.48,176.69 163.48,176.05 163.99,175.55 163.99,174.28 161.96,172.24 161.96,169.23 160.9,168.18 155.61,168.18 155.1,168.69 155.1,173.98 155.99,174.87 155.99,177.11 155.1,178 155.1,185.07 155.55,185.52 162.68,185.52
PHASE1 on BOTTOM (solid shape): 162.85,185.1 162.85,180.45 163.68,179.61 167.8,179.61 167.81,179.6 167.91,179.6 168.43,179.08 168.43,176.71 168.16,176.44 166.28,176.44 161.96,172.12 161.96,169.2 160.94,168.18 157,168.18 156.94,168.24 155.54,168.24 155.1,168.69 155.1,174.02 155.99,174.91 155.99,177.07 155.1,177.96 155.1,185.07 155.61,185.58 162.36,185.58
PHASE1 on PWR (solid shape): 162.85,185.17 162.85,180.47 163.7,179.61 167.9,179.61 168.43,179.07 168.43,176.72 168.15,176.44 166.15,176.44 165.01,177.58 164.37,177.58 163.48,176.69 163.48,176.05 163.99,175.55 163.99,174.18 161.96,172.15 161.96,169.23 160.91,168.18 155.64,168.18 155.1,168.72 155.1,173.99 155.99,174.88 155.99,177.1 155.1,177.99 155.1,185.04 155.64,185.58 162.43,185.58
PHASE2 on TOP (solid shape): 180.81,185.4 180.81,183.74 181.52,183.04 181.52,181.77 182.4,180.88 186.18,180.88 186.6,180.46 186.6,178.47 185.45,177.32 184.82,177.32 184.18,176.69 184.18,176.12 181.9,173.83 181.9,168.35 181.48,167.93 176.21,167.93 175.69,168.45 175.69,174.4 176.18,174.9 176.18,176.97 175.67,177.48 175.67,185.03 176.18,185.54 180.67,185.54
PHASE2 on BOTTOM (solid shape): 180.75,185.2 180.75,183.87 181.55,183.07 181.52,183.04 181.52,181.77 182.4,180.88 186.21,180.88 186.6,180.5 186.6,178.47 181.9,173.77 181.9,168.31 181.52,167.93 176.18,167.93 175.67,168.43 175.67,174.38 176.18,174.89 176.18,176.97 175.67,177.48 175.67,185.07 176.18,185.58 180.37,185.58
PHASE2 on PWR (solid shape): 180.75,185.17 180.75,183.77 181.52,183.01 181.52,181.74 182.37,180.88 186.18,180.88 186.6,180.47 186.6,178.5 185.68,177.58 185.07,177.58 184.18,176.69 184.18,176.09 181.9,173.8 181.9,168.34 181.48,167.93 176.21,167.93 175.67,168.47 175.67,174.37 176.18,174.88 176.18,176.97 175.67,177.48 175.67,185.04 176.21,185.58 180.34,185.58
PHASE3 on TOP (solid shape): 224.19,177.96 224.19,165.01 223.87,164.69 215.42,164.69 214.92,165.2 214.92,169.07 215.55,169.7 215.55,171.1 214.92,171.74 213.39,171.74 211.11,174.02 211.11,175.78 211.5,176.17 214.41,176.17 214.64,175.93 214.64,174.7 215.2,174.15 216.44,174.15 216.45,174.16 216.5,174.16 217.58,175.24 217.58,175.55 217.71,175.67 218.6,175.67 219.36,176.44 219.36,177.96 219.87,178.47 223.68,178.47
PHASE3 on BOTTOM (solid shape): 224.19,177.32 224.19,165.01 223.81,164.62 216.31,164.62 215.55,165.39 215.55,169.58 211.11,174.02 211.11,175.8 211.49,176.18 214.41,176.18 214.65,175.94 214.65,174.7 215.2,174.15 216.44,174.15 217.84,175.55 218.52,175.55 219.36,176.38 219.36,177.5 219.56,177.71 223.81,177.71
PHASE3 on PWR (solid shape): 224.19,177.93 224.19,165.04 223.78,164.62 215.33,164.62 214.92,165.04 214.92,169.08 215.55,169.7 215.55,171.1 214.92,171.72 213.5,171.72 213.47,171.69 211.11,174.05 211.11,175.77 211.52,176.18 214.38,176.18 214.61,175.95 214.61,174.75 215.22,174.15 216.47,174.15 217.87,175.55 218.5,175.55 219.36,176.4 219.36,177.93 219.9,178.47 223.65,178.47
PHASE4 on TOP (solid shape): 142.78,185.26 142.78,180.69 143.35,180.12 148.83,180.12 149.26,179.69 149.26,176.82 148.88,176.44 146.21,176.44 145.32,177.32 144.94,177.32 144.3,176.69 144.3,176.31 144.94,175.67 144.94,174.71 142.02,171.79 142.02,168.84 140.76,167.58 136.27,167.58 136.05,167.8 136.05,174.02 136.81,174.78 136.81,176.94 136.01,177.74 136.01,184.4 137.19,185.58 142.46,185.58
PHASE4 on BOTTOM (solid shape): 142.78,185.26 142.78,180.75 143.42,180.12 148.88,180.12 149.26,179.74 149.26,176.82 148.88,176.44 147.61,176.44 145.45,174.28 144.56,174.28 142.02,171.74 142.02,168.82 140.75,167.55 136.3,167.55 135.92,167.93 135.92,173.9 136.81,174.78 136.81,176.94 135.92,177.83 135.92,184.31 137.19,185.58 142.46,185.58
PHASE4 on PWR (solid shape): 142.78,185.29 142.78,180.72 143.38,180.12 148.85,180.12 149.26,179.71 149.26,176.82 148.88,176.44 146.21,176.44 145.32,177.32 144.94,177.32 144.3,176.69 144.3,176.31 144.94,175.67 144.94,174.53 144.69,174.28 144.53,174.28 142.02,171.77 142.02,168.85 140.72,167.55 136.33,167.55 136.05,167.83 136.05,173.99 136.81,174.75 136.81,176.98 136.02,177.74 136.02,184.38 137.22,185.58 142.5,185.58
SPKR_C on TOP (solid shape): 232.82,106.46 232.82,104.3 232.57,104.05 229.9,104.05 229.52,104.43 229.52,106.1 230.28,106.86 232.42,106.86
SWN1 on TOP (solid shape): 72.84,56.13 72.84,51.04 72.04,50.24 72.04,48.67 72.82,47.9 72.82,42.84 72.42,42.45 71.13,42.45 70.01,41.33 70.01,40.7 69.6,40.29 65.56,40.29 65.31,40.55 65.31,41.82 64.73,42.4 63.68,42.4 62.95,41.66 62.19,41.66 60.74,43.11 60.74,47.28 60.99,47.53 61.25,47.53 62.52,46.26 63.02,46.26 63.41,45.88 63.79,45.88 64.04,46.13 64.04,46.51 63.66,46.9 63.66,47.15 63.41,47.4 63.41,48.17 62.64,48.93 62.64,54.52 64.55,56.42 72.55,56.42
SWN1 on BOTTOM (solid shape): 72.84,56.13 72.84,51.04 72.04,50.24 72.04,48.67 72.83,47.89 72.83,42.7 72.57,42.45 71.13,42.45 70.01,41.33 70.01,40.77 69.53,40.29 65.74,40.29 65.36,40.67 65.36,41.76 64.55,42.58 63.72,42.58 62.2,44.1 62.2,48.99 62.64,49.44 62.64,54.52 64.55,56.42 72.55,56.42
SWN1 on PWR (solid shape): 72.86,56.08 72.85,56.03 72.85,51.04 72.04,50.23 72.04,48.64 72.83,47.86 72.83,42.71 72.57,42.45 71.12,42.45 70.01,41.34 70.01,40.7 69.6,40.29 65.76,40.29 65.36,40.69 65.36,41.8 64.76,42.4 63.68,42.4 62.94,41.66 62.17,41.66 60.74,43.09 60.74,47.5 60.9,47.66 61.14,47.66 62.52,46.29 63.02,46.29 63.43,45.88 63.79,45.88 64.04,46.13 64.04,46.51 63.63,46.92 63.63,47.17 63.41,47.4 63.41,48.17 62.64,48.93 62.64,54.48 64.58,56.42 72.52,56.42
SWN2 on TOP (solid shape): 53.5,19.08 57.31,19.08 57.44,18.96 57.44,17.56 57.94,17.05 60.1,17.05 60.99,17.94 60.99,18.96 61.12,19.08 64.04,19.08 64.17,18.96 64.17,15.53 60.74,12.1 59.21,12.1 57.82,13.49 57.31,13.49 56.8,12.99 56.8,12.48 58.83,10.45 58.83,10.26 57.37,8.8 55.15,8.8 52.99,6.64 48.55,6.64 48.17,7.02 48.17,11.77 48.47,12.07 48.47,14.46 48.17,14.76 48.17,19.97 48.42,20.23 52.36,20.23
SWN2 on BOTTOM (solid shape): 58.6,14.26 58.6,13.8 58.76,13.65 59.21,13.65 59.47,13.39 59.47,11.39 58.81,10.73 50.43,10.73 49.94,11.21 49.94,14.66 50.87,15.59 57.27,15.59
SWN2 on PWR (solid shape): 53.47,19.08 57.02,19.08 57.31,18.8 57.31,17.65 57.91,17.05 60.13,17.05 60.99,17.91 60.99,18.92 61.15,19.08 63.88,19.08 64.17,18.8 64.17,15.56 60.67,12.06 59.25,12.06 57.82,13.49 57.31,13.49 56.8,12.99 56.8,12.48 58.83,10.45 58.83,10.22 57.41,8.8 55.12,8.8 52.96,6.64 48.7,6.64 48.11,7.23 48.11,11.74 48.47,12.09 48.47,14.47 48.11,14.82 48.11,19.72 48.59,20.23 52.33,20.23
SYS_FAN_P2 on TOP (solid shape): 121.57,197.01 121.57,195.61 120.94,194.98 120.94,193.07 120.68,192.82 119.67,192.82 119.29,193.2 119.29,194.98 119.54,195.23 119.54,196.5 120.17,197.14 121.44,197.14
SYS_FAN_P2 on TOP (solid shape): 118.02,180.75 118.02,174.66 117.38,174.02 108.54,174.02 106.2,176.36 106.2,177.88 115.44,177.88 115.44,179.59 113.73,179.59 113.73,177.88 106.2,177.88 106.2,178.72 108.9,178.72 108.91,178.64 108.92,178.56 108.94,178.48 108.96,178.41 109,178.33 109.04,178.26 109.09,178.2 109.15,178.14 109.21,178.09 109.27,178.04 109.34,178 109.42,177.96 109.49,177.94 109.57,177.92 109.65,177.91 109.74,177.91 109.82,177.91 109.9,177.93 109.97,177.95 110.05,177.98 110.12,178.02 110.19,178.06 110.25,178.11 110.31,178.17 110.36,178.23 110.41,178.3 110.45,178.37 110.48,178.44 110.5,178.52 110.52,178.6 110.53,178.68 110.53,178.76 110.52,178.84 110.5,178.92 110.48,179 110.45,179.07 110.41,179.15 110.36,179.21 110.31,179.28 110.25,179.33 110.19,179.38 110.12,179.43 110.05,179.46 109.97,179.49 109.9,179.52 109.82,179.53 109.74,179.54 109.65,179.53 109.57,179.52 109.49,179.51 109.42,179.48 109.34,179.45 109.27,179.41 109.21,179.36 109.15,179.3 109.09,179.24 109.04,179.18 109,179.11 108.96,179.04 108.94,178.96 108.92,178.88 108.91,178.8 108.9,178.72 106.2,178.72 106.2,180.25 107.86,181.9 116.87,181.9
SYS_FAN_P2 on BOTTOM (solid shape): outline of 159 points within 106.2,177.32 120.81,194.22
UGND1 on TOP (solid shape): 109.51,213.67 109.51,212.38 108.87,211.74 108.24,211.74 108.11,211.87 108.11,213.27 108.08,213.29 108.08,213.49 108.39,213.8 108.89,213.8 108.89,213.8 109.38,213.8
UGND1 on TOP (solid shape): 125,243.11 125,237.4 121.95,234.35 119.79,234.35 118.27,235.87 109.56,235.87 107.87,234.18 106.37,234.18 105.82,234.73 103.54,234.73 103.16,235.11 103.16,238.54 105.44,240.82 105.44,243.11 105.82,243.49 124.62,243.49
UGND1 on TOP (solid shape): 119.03,215.17 119.67,215.17 119.92,214.92 119.92,211.49 119.79,211.36 118.1,211.36 118.1,211.36 117.79,211.36 117.25,211.89 117.25,213.77 116.75,214.28 116.75,214.59 117.74,214.59 117.74,213.74 118.24,213.74 118.24,213.47 118.22,213.45 118.18,213.41 118.15,213.36 118.12,213.3 118.1,213.25 118.09,213.19 118.09,213.13 118.1,213.07 118.11,213.02 118.13,212.96 118.16,212.91 118.19,212.86 118.23,212.82 118.28,212.78 118.33,212.75 118.38,212.73 118.44,212.71 118.49,212.71 118.55,212.71 118.61,212.71 118.67,212.73 118.72,212.75 118.77,212.78 118.82,212.82 118.86,212.86 118.89,212.91 118.92,212.96 118.94,213.02 118.95,213.07 118.96,213.13 118.95,213.19 118.94,213.25 118.92,213.3 118.9,213.36 118.86,213.41 118.83,213.45 118.8,213.47 118.8,214.28 118.8,214.29 118.8,214.59 118.49,214.59 118.39,214.7 118.15,214.7 118.05,214.59 116.75,214.59 116.75,215.04 116.87,215.17 119.03,215.17
UGND1 on BOTTOM (solid shape): 125,242.86 125,237.4 124.11,236.51 124.11,234.09 123.86,233.84 119.79,233.84 117.76,235.87 108.62,235.87 107.03,234.28 105.51,234.28 104.81,234.98 103.66,234.98 103.16,235.49 103.16,238.54 105.44,240.82 105.44,242.98 105.95,243.49 123.22,243.49 124.37,243.49
UGND1 on PWR (solid shape): outline of 3446 points within 89.44,209.84 126.65,243.49
V_0P9_LAN on TOP (solid shape): 75.22,209.2 75.22,206.92 75.47,206.66 76.23,206.66 76.36,206.79 76.36,207.3 76.61,207.55 82.58,207.55 82.84,207.3 82.84,205.65 82.07,204.88 72.8,204.88 72.68,205.01 72.68,208.95 73.18,209.46 74.96,209.46
V_0P9_LAN on BOTTOM (solid shape): 69.12,217.58 69.12,213.27 68.87,213.01 67.98,213.01 67.72,213.27 67.72,217.58 67.98,217.84 68.87,217.84
V_1P05_ME_5V_IN on TOP (solid shape): 81.82,63.41 81.82,62.77 81.77,62.57 81.82,62.36 81.82,62.01 81.44,61.63 81.44,61.37 81.44,60.61 81.44,59.85 81.69,59.6 82.33,59.6 82.84,59.09 82.84,54.39 82.46,54.01 80.68,54.01 80.42,54.26 80.42,58.96 80.42,58.96 80.42,59.34 79.28,60.48 79.28,61.04 79.28,61.04 79.28,61.63 79.41,61.75 80.04,61.75 80.17,61.88 80.17,62.36 80.17,63.53 80.42,63.79 81.44,63.79
V_ME_PHASE on TOP (solid shape): 76.99,64.8 76.99,64.04 77.25,63.79 78.26,63.79 78.39,63.66 78.39,63.15 78.26,63.02 77.02,63.02 76.79,63.25 72.45,63.25 72.3,63.41 72.3,64.8 72.55,65.06 76.74,65.06

Small or netless copper shapes (teardrops, artwork), in the pictures only: 322 on TOP, 10 on BOTTOM

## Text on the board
Ref Des/Silkscreen Top: S | I | A7 | A6 | A4 | J | B | A1 | A | K | N | C1 | M | O | P | C | Q | D | A3 | L | R | E | U | T | G | w | C5 | H | B1 | V | x | A8 | F | B85H3_AM | Q87H3_AM | V:1.0 | 15-ET5-011000
User.14: 15-ET5-011000 | Q87_B85H3-AM V1.0 TOP
User.15: 15-ET5-011000 | Q87_B85H3-AM V1.0 BOTTOM
User.39: 57
User.45: FIGURE | SIZE | 10.0 | 12.0 | 14.0 | 16.0 | 20.0 | 26.0 | 28.0 | 30.0 | 32.0 | 34.0 | 36.0 | 37.0 | 40.0 | 43.0 | 44.0 | 48.0 | 54.0 | 55.0 | 56.0 | 64.0 | 68.0 | 76.0 | 92.0 | 98.0 | 128.0 | 51.0 | 93.0 | 97.0 | 104.0 | 124.0 | 150.0 | 156.0 | 160.0 | 47.0x32.0 | 68.0x28.0 | 78.0x60.0 | 80.0x68.0 | 82.0x64.0 | 88.0x28.0 | 94.0x76.0 | 96.0x72.0 | DRILL CHART: TOP to BOTTOM | ALL UNITS ARE IN MILS | TOLERANCE | +3.0/-3.0 | +4.0/-0.0 | +4.0/-4.0 | PLATED | NON-PLATED | QTY | 364 | 4813 | 64 | 61 | 44 | 2 | 1330 | 35 | 21 | 30 | 16 | 18 | 391 | 8 | 25 | 11 | 10 | 12 | 4 | 1 | 5 | 7 | 6 | 3
